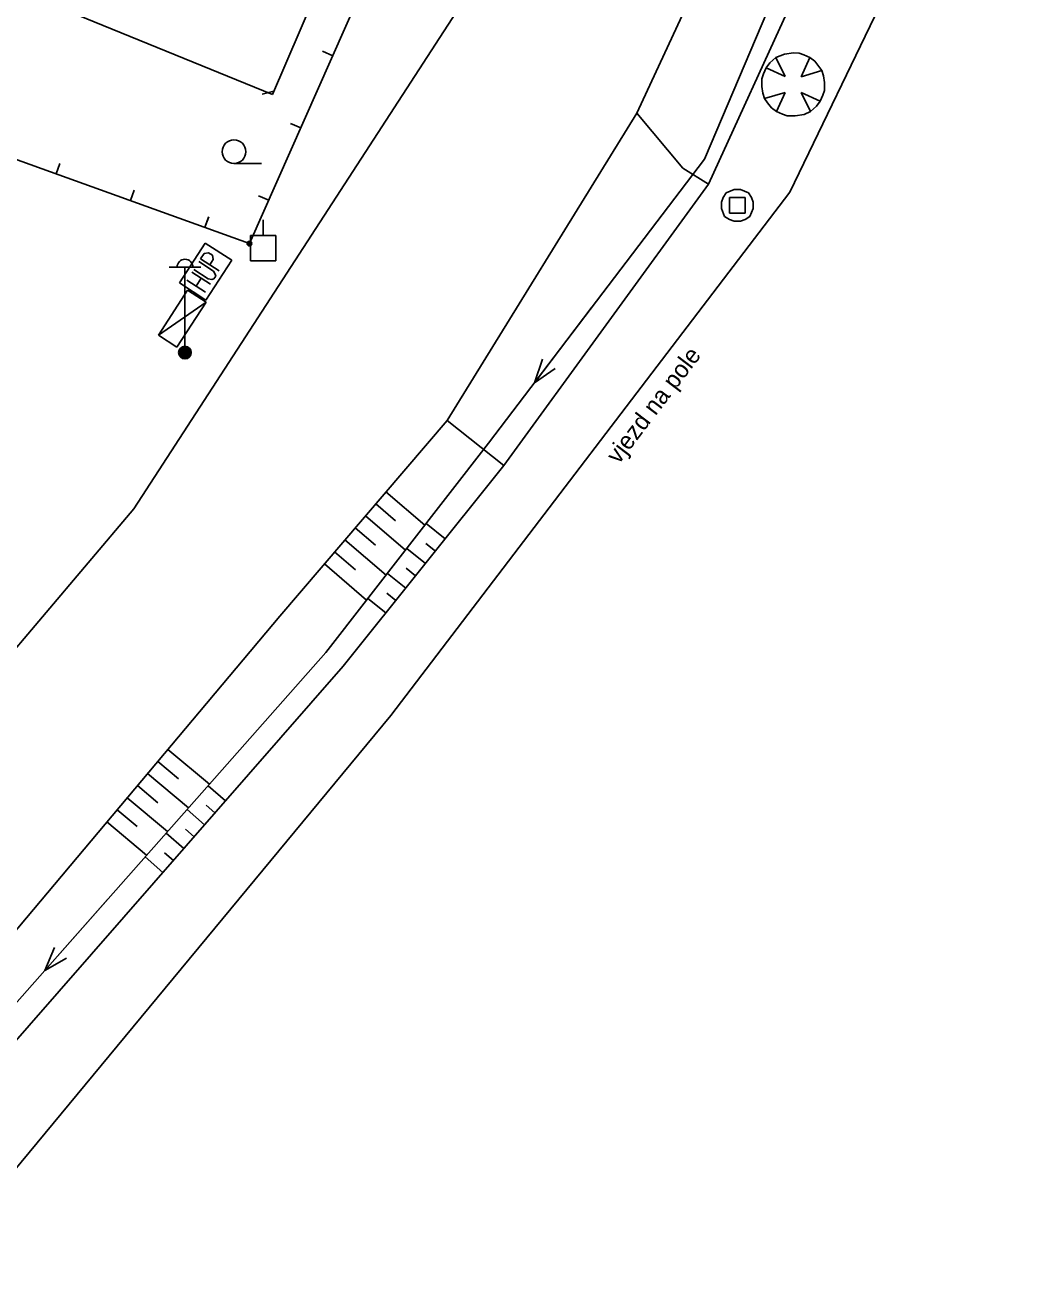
# Model space of a CAD drawing. Extents: x -559554 to -559082, y -1075950 to -1075150.
# Drawn here: x -559240.7 to -559209.31, y -1075503.31 to -1075463.29 of the extents above; entities that cross this region are included whole.
import ezdxf

# ---------------------------------------------------------------- set-up
doc = ezdxf.new("R2010")
doc.units = 0
doc.layers.add('kl', color=7, linetype='Continuous')
doc.layers.add('PF', color=7, linetype='Continuous')

msp = doc.modelspace()

# ---------------------------------------------------------------- linework, layer by layer
at = {"layer": 'kl'}
for p, q in [((-559221.36, -1075466.07), (-559214.28, -1075450.87)), ((-559219.22, -1075467.53), (-559212.6, -1075451.95)), ((-559219.09, -1075468.32), (-559211.92, -1075452.62)), ((-559216.52, -1075468.57), (-559209.31, -1075453.63)), ((-559233.61, -1075470.2), (-559228.94, -1075459.66)), ((-559237.27, -1075478.6), (-559226.81, -1075462.47)), ((-559230.976, -1075464.257), (-559231.296, -1075464.115)), ((-559216.958, -1075464.315), (-559216.687, -1075464.207)), ((-559216.687, -1075464.207), (-559216.407, -1075464.169)), ((-559216.407, -1075464.169), (-559216.227, -1075464.18)), ((-559216.227, -1075464.18), (-559216.077, -1075464.231)), ((-559216.077, -1075464.231), (-559215.888, -1075464.312)), ((-559217.351, -1075464.833), (-559217.27, -1075464.643)), ((-559217.27, -1075464.643), (-559217.149, -1075464.484)), ((-559217.27, -1075464.643), (-559216.661, -1075464.917)), ((-559217.149, -1075464.484), (-559216.958, -1075464.315)), ((-559216.661, -1075464.917), (-559216.958, -1075464.315)), ((-559215.888, -1075464.312), (-559216.161, -1075464.92)), ((-559215.888, -1075464.312), (-559215.728, -1075464.433)), ((-559215.728, -1075464.433), (-559215.599, -1075464.594)), ((-559215.599, -1075464.594), (-559215.51, -1075464.724)), ((-559217.403, -1075465.233), (-559217.402, -1075464.983)), ((-559217.402, -1075464.983), (-559217.351, -1075464.833)), ((-559216.161, -1075464.92), (-559215.51, -1075464.724)), ((-559215.51, -1075464.724), (-559215.451, -1075464.895)), ((-559215.451, -1075464.895), (-559215.422, -1075465.105)), ((-559215.422, -1075465.105), (-559215.424, -1075465.355)), ((-559233.211, -1075465.471), (-559232.84, -1075465.382)), ((-559217.375, -1075465.443), (-559217.403, -1075465.233)), ((-559217.316, -1075465.613), (-559217.375, -1075465.443)), ((-559216.664, -1075465.417), (-559217.316, -1075465.613)), ((-559216.938, -1075466.026), (-559216.664, -1075465.417)), ((-559215.868, -1075466.022), (-559216.164, -1075465.42)), ((-559216.164, -1075465.42), (-559215.556, -1075465.694)), ((-559215.475, -1075465.505), (-559215.556, -1075465.694)), ((-559215.424, -1075465.355), (-559215.475, -1075465.505)), ((-559217.226, -1075465.744), (-559217.316, -1075465.613)), ((-559217.097, -1075465.905), (-559217.226, -1075465.744)), ((-559216.938, -1075466.026), (-559217.097, -1075465.905)), ((-559215.677, -1075465.853), (-559215.868, -1075466.022)), ((-559215.556, -1075465.694), (-559215.677, -1075465.853)), ((-559221.36, -1075466.07), (-559227.36, -1075475.8)), ((-559219.9, -1075467.81), (-559221.36, -1075466.07)), ((-559216.749, -1075466.107), (-559216.938, -1075466.026)), ((-559216.599, -1075466.158), (-559216.749, -1075466.107)), ((-559216.349, -1075466.159), (-559216.599, -1075466.158)), ((-559216.069, -1075466.121), (-559216.349, -1075466.159)), ((-559215.868, -1075466.022), (-559216.069, -1075466.121)), ((-559233.61, -1075470.2), (-559243.989, -1075466.459)), ((-559231.989, -1075466.542), (-559232.309, -1075466.401)), ((-559239.724, -1075467.996), (-559239.606, -1075467.666)), ((-559234.1, -1075467.667), (-559233.225, -1075467.667)), ((-559226.05, -1075476.52), (-559219.22, -1075467.53)), ((-559219.9, -1075467.81), (-559219.09, -1075468.32)), ((-559237.373, -1075468.843), (-559237.254, -1075468.514)), ((-559233.002, -1075468.828), (-559233.322, -1075468.686)), ((-559229.14, -1075485.14), (-559216.52, -1075468.57)), ((-559225.56, -1075477.22), (-559219.09, -1075468.32)), ((-559218.63, -1075468.74), (-559218.53, -1075468.59)), ((-559218.53, -1075468.59), (-559218.28, -1075468.49)), ((-559218.28, -1075468.49), (-559218.08, -1075468.49)), ((-559218.08, -1075468.49), (-559217.83, -1075468.59)), ((-559217.83, -1075468.59), (-559217.73, -1075468.74)), ((-559218.68, -1075468.89), (-559218.63, -1075468.74)), ((-559218.68, -1075469.09), (-559218.68, -1075468.89)), ((-559218.58, -1075469.34), (-559218.68, -1075469.09)), ((-559218.43, -1075468.74), (-559217.93, -1075468.74)), ((-559218.43, -1075469.24), (-559218.43, -1075468.74)), ((-559217.93, -1075468.74), (-559217.93, -1075469.24)), ((-559217.68, -1075469.09), (-559217.78, -1075469.34)), ((-559217.73, -1075468.74), (-559217.68, -1075468.89)), ((-559217.68, -1075468.89), (-559217.68, -1075469.09)), ((-559235.021, -1075469.691), (-559234.902, -1075469.362)), ((-559235.017, -1075469.68), (-559234.895, -1075469.352)), ((-559233.18, -1075469.95), (-559233.18, -1075469.45)), ((-559218.43, -1075469.44), (-559218.58, -1075469.34)), ((-559217.93, -1075469.24), (-559218.43, -1075469.24)), ((-559218.28, -1075469.49), (-559218.43, -1075469.44)), ((-559218.08, -1075469.49), (-559218.28, -1075469.49)), ((-559217.93, -1075469.44), (-559218.08, -1075469.49)), ((-559217.78, -1075469.34), (-559217.93, -1075469.44)), ((-559235.827, -1075471.445), (-559235.01, -1075470.186)), ((-559235.01, -1075470.186), (-559234.171, -1075470.73)), ((-559233.663, -1075470.185), (-559233.647, -1075470.167)), ((-559233.588, -1075470.252), (-559233.663, -1075470.185)), ((-559233.661, -1075470.22), (-559233.624, -1075470.254)), ((-559233.647, -1075470.167), (-559233.572, -1075470.233)), ((-559233.63, -1075470.148), (-559233.595, -1075470.146)), ((-559233.555, -1075470.214), (-559233.63, -1075470.148)), ((-559233.624, -1075470.254), (-559233.588, -1075470.252)), ((-559233.595, -1075470.146), (-559233.557, -1075470.179)), ((-559233.58, -1075469.95), (-559232.78, -1075469.95)), ((-559233.58, -1075470.75), (-559233.58, -1075469.95)), ((-559233.572, -1075470.233), (-559233.555, -1075470.214)), ((-559232.78, -1075469.95), (-559232.78, -1075470.75)), ((-559235.157, -1075470.687), (-559235.048, -1075470.519)), ((-559234.569, -1075471.068), (-559235.157, -1075470.687)), ((-559235.048, -1075470.519), (-559234.91, -1075470.49)), ((-559234.91, -1075470.49), (-559234.784, -1075470.572)), ((-559234.754, -1075470.71), (-559234.863, -1075470.878)), ((-559234.784, -1075470.572), (-559234.754, -1075470.71)), ((-559235.15, -1075470.95), (-559236.15, -1075470.95)), ((-559235.65, -1075470.95), (-559235.65, -1075473.45)), ((-559234.841, -1075471.488), (-559235.429, -1075471.107)), ((-559235.374, -1075471.023), (-559234.913, -1075471.322)), ((-559234.75, -1075471.07), (-559235.211, -1075470.771)), ((-559234.171, -1075470.73), (-559234.988, -1075471.989)), ((-559234.693, -1075471.167), (-559234.75, -1075471.07)), ((-559232.78, -1075470.75), (-559233.58, -1075470.75)), ((-559234.988, -1075471.989), (-559235.827, -1075471.445)), ((-559235.592, -1075471.358), (-559235.005, -1075471.739)), ((-559235.298, -1075471.549), (-559235.135, -1075471.297)), ((-559234.913, -1075471.322), (-559234.802, -1075471.335)), ((-559234.802, -1075471.335), (-559234.733, -1075471.32)), ((-559234.733, -1075471.32), (-559234.678, -1075471.236)), ((-559234.678, -1075471.236), (-559234.693, -1075471.167)), ((-559236.491, -1075473.101), (-559235.566, -1075471.674)), ((-559235.566, -1075471.674), (-559234.979, -1075472.055)), ((-559236.491, -1075473.101), (-559234.979, -1075472.055)), ((-559234.979, -1075472.055), (-559235.904, -1075473.482)), ((-559222.779, -1075472.215), (-559224.594, -1075474.604)), ((-559235.904, -1075473.482), (-559236.491, -1075473.101)), ((-559235.53, -1075473.49), (-559235.77, -1075473.49)), ((-559235.45, -1075473.65), (-559235.85, -1075473.65)), ((-559235.846, -1075473.61), (-559235.454, -1075473.61)), ((-559235.846, -1075473.69), (-559235.454, -1075473.69)), ((-559235.468, -1075473.57), (-559235.832, -1075473.57)), ((-559235.468, -1075473.73), (-559235.832, -1075473.73)), ((-559235.81, -1075473.53), (-559235.49, -1075473.53)), ((-559235.81, -1075473.77), (-559235.49, -1075473.77)), ((-559235.53, -1075473.81), (-559235.77, -1075473.81)), ((-559224.594, -1075474.604), (-559224.34, -1075473.856)), ((-559224.594, -1075474.604), (-559223.942, -1075474.158)), ((-559227.36, -1075475.8), (-559232.65, -1075481.99)), ((-559225.56, -1075477.22), (-559227.36, -1075475.8)), ((-559231.19, -1075483.14), (-559226.05, -1075476.52)), ((-559230.65, -1075483.58), (-559225.56, -1075477.22)), ((-559229.292, -1075478.061), (-559228.062, -1075479.112)), ((-559251.14, -1075494.97), (-559237.27, -1075478.6)), ((-559229.617, -1075478.441), (-559228.993, -1075478.974)), ((-559229.942, -1075478.821), (-559228.676, -1075479.903)), ((-559227.419, -1075479.543), (-559228.022, -1075479.06)), ((-559230.267, -1075479.201), (-559229.625, -1075479.75)), ((-559230.591, -1075479.581), (-559229.29, -1075480.693)), ((-559228.043, -1075480.323), (-559228.635, -1075479.85)), ((-559227.731, -1075479.933), (-559228.03, -1075479.694)), ((-559230.916, -1075479.961), (-559230.257, -1075480.525)), ((-559231.241, -1075480.341), (-559229.904, -1075481.484)), ((-559228.668, -1075481.104), (-559229.249, -1075480.64)), ((-559228.356, -1075480.714), (-559228.649, -1075480.479)), ((-559229.293, -1075481.885), (-559229.862, -1075481.43)), ((-559228.981, -1075481.494), (-559229.268, -1075481.264)), ((-559232.65, -1075481.99), (-559247.01, -1075499.1)), ((-559246.52, -1075500.49), (-559231.19, -1075483.14)), ((-559246.05, -1075501.21), (-559230.65, -1075483.58)), ((-559244.19, -1075503.31), (-559229.14, -1075485.14)), ((-559236.19, -1075486.208), (-559234.876, -1075487.311)), ((-559236.511, -1075486.591), (-559235.859, -1075487.139)), ((-559236.833, -1075486.974), (-559235.538, -1075488.061)), ((-559237.154, -1075487.357), (-559236.512, -1075487.896)), ((-559234.373, -1075487.842), (-559234.921, -1075487.363)), ((-559237.476, -1075487.74), (-559236.2, -1075488.811)), ((-559237.797, -1075488.123), (-559237.164, -1075488.654)), ((-559235.031, -1075488.595), (-559235.584, -1075488.113)), ((-559234.702, -1075488.219), (-559234.977, -1075487.978)), ((-559238.119, -1075488.506), (-559236.863, -1075489.56)), ((-559235.689, -1075489.348), (-559236.246, -1075488.862)), ((-559235.36, -1075488.972), (-559235.637, -1075488.73)), ((-559236.018, -1075489.725), (-559236.297, -1075489.481)), ((-559236.347, -1075490.102), (-559236.908, -1075489.611)), ((-559238.1, -1075490.96), (-559240.086, -1075493.208)), ((-559240.086, -1075493.208), (-559239.777, -1075492.481)), ((-559240.086, -1075493.208), (-559239.402, -1075492.812))]:
    msp.add_line(p, q, dxfattribs=at)
for centre, radius in [((-559234.1, -1075467.293), 0.375), ((-559233.61, -1075470.2), 0.075), ((-559235.65, -1075473.649), 0.2)]:
    msp.add_circle(centre, radius, dxfattribs=at)
msp.add_arc((-559235.65, -1075470.949), 0.25, 0, 180, dxfattribs=at)
at = {"layer": 'PF'}
for p in [(-559226.26, -1075450.1), (-559242.323, -1075461.626)]:
    msp.add_line(p, (-559232.884, -1075465.484), dxfattribs=at)

# ---------------------------------------------------------------- texts
at = {"layer": 'kl'}
msp.add_text('vjezd na pole', height=0.5525, rotation=52.7748, dxfattribs=at).set_placement((-559221.933, -1075477.207))

doc.saveas('drawing.dxf')
